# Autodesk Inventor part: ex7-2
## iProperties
Author: Administrator
Created: 2001-03
Part Number: ex7-2
Document SubType Name: Modeling
Designer: Administrator
Control State: 0
Master: False
Checked Out: False
PropertySet Name: Design Tracking Control
Shininess: 20.0
PropertySet Name: _Private Model Information
Density: 0.0
Volumn: 0.0
Area: 0.0
PropertySet Name: Model Information
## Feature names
1. Derived Body1 [Tagging]
